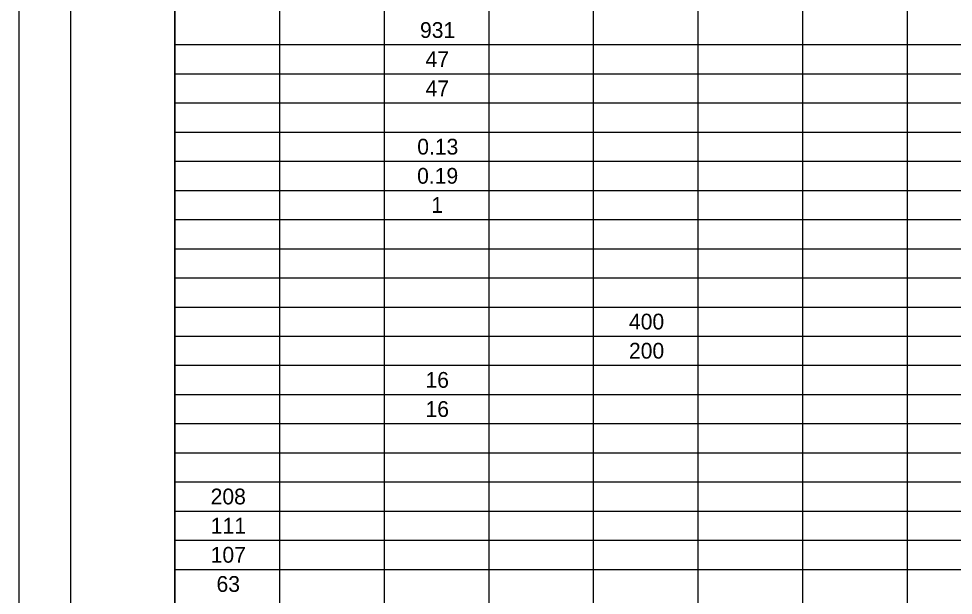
# Model space of a CAD drawing. Extents: x 0 to 34, y 0 to 22.
# Drawn here: x 0 to 8.98, y 10.89 to 16.43 of the extents above; entities that cross this region are included whole.
import ezdxf

# ---------------------------------------------------------------- set-up
doc = ezdxf.new("R2010")
doc.units = 0
for name, color, linetype in [('Default', 7, 'Continuous'), ('SH_Border', 7, 'Continuous'), ('SH_Cut_Line', 7, 'Continuous')]:
    doc.layers.add(name, color=color, linetype=linetype)

msp = doc.modelspace()

# ---------------------------------------------------------------- linework, layer by layer
at = {"layer": 'Default'}
for p, q in [((1.5, 21.5), (1.5, 0.5)), ((2.5046, 20.94), (2.5046, 0.5)), ((3.5092, 20.94), (3.5092, 0.5)), ((4.5138, 20.94), (4.5138, 0.5)), ((5.5184, 20.94), (5.5184, 0.5)), ((6.5229, 20.94), (6.5229, 0.5)), ((7.5275, 20.94), (7.5275, 0.5)), ((8.5321, 20.94), (8.5321, 0.5)), ((1.5, 16.18), (32, 16.18)), ((1.5, 15.9), (32, 15.9)), ((1.5, 15.62), (32, 15.62)), ((1.5, 15.34), (32, 15.34)), ((1.5, 15.06), (32, 15.06)), ((1.5, 14.78), (32, 14.78)), ((1.5, 14.5), (32, 14.5)), ((1.5, 14.22), (32, 14.22)), ((1.5, 13.94), (32, 13.94)), ((1.5, 13.66), (32, 13.66)), ((1.5, 13.38), (32, 13.38)), ((1.5, 13.1), (32, 13.1)), ((1.5, 12.82), (32, 12.82)), ((1.5, 12.54), (32, 12.54)), ((1.5, 12.26), (32, 12.26)), ((1.5, 11.98), (32, 11.98)), ((1.5, 11.7), (32, 11.7)), ((1.5, 11.42), (32, 11.42)), ((1.5, 11.14), (32, 11.14))]:
    msp.add_line(p, q, dxfattribs=at)
at = {"layer": 'SH_Border'}
for points in [[(0.5, 21.5), (1.5, 21.5), (1.5, 0.5), (0.5, 0.5)], [(1.5, 21.5), (33.5, 21.5), (33.5, 0.5), (1.5, 0.5)]]:
    msp.add_lwpolyline(points, close=True, dxfattribs=at)
at = {"layer": 'SH_Cut_Line'}
msp.add_lwpolyline([(0, 0), (34, 0), (34, 22), (0, 22)], close=True, dxfattribs=at)

# ---------------------------------------------------------------- texts
at = {"layer": 'Default'}
for s, height, p in [('931', 0.15153, (3.8541, 16.2442)), ('47', 0.15153, (3.9076, 15.9642)), ('47', 0.15153, (3.9076, 15.6842)), ('0.13', 0.15153, (3.8276, 15.1242)), ('0.19', 0.15153, (3.8265, 14.8442)), ('1', 0.1515, (3.9629, 14.5642)), ('400', 0.15153, (5.8611, 13.4442)), ('200', 0.15153, (5.8611, 13.1642)), ('16', 0.15153, (3.9069, 12.8842)), ('16', 0.15153, (3.9069, 12.6042)), ('208', 0.15153, (1.8435, 11.7642)), ('111', 0.15153, (1.8449, 11.4842)), ('107', 0.15153, (1.844, 11.2042)), ('63', 0.15153, (1.9, 10.9242))]:
    msp.add_text(s, height=height, dxfattribs=at).set_placement(p)

doc.saveas('drawing.dxf')
